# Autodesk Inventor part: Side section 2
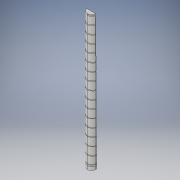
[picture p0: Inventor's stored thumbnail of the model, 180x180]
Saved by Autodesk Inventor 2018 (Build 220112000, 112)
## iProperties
Created: 2018-10
Part Number: Side section 2
Material: Generic
Document SubType Name: Modeling
Designer: johne
Density: 1 g/cm^3
Appearance: Default
Author: johne
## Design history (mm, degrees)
sketch "Sketch1"
  geometry: L1 (0, 0)-(25.4, 0); L2 (25.4, 0)-(25.4, -76.2); L3 (25.4, -76.2)-(0, -76.2); L4 (0, -76.2)-(0, 0)
  constraints: 8 end point, 2 parallel, 1 horizontal, 1 perpendicular
  dimensions: "d0" = 25.4 distance of L2.end L3.end; "d1" = 76.2 distance of L1.end L2.end
extrude "Extrusion1" new body sketch "Sketch1" distance "d2" = 25.4; taper "d3" = 0 deg
sketch "Sketch3"
  geometry: L1 (-2.627, -64.34)-(-23.226, -64.34); L2 (-23.226, -64.34)-(-23.226, -10.419); L3 (-23.226, -10.419)-(-2.627, -10.419); L4 (-2.627, -10.419)-(-2.627, -64.34); 1 further point
  constraints: 8 end point, 2 parallel, 1 horizontal, 1 perpendicular
extrude "Extrusion2" join sketch "Sketch3" distance "d4" = 25.4; taper "d5" = 0 deg
sketch "Sketch4"
  geometry: L1 (9.188, -40.142)-(9.188, 0); L2 (65.781, 0)-(-10.419, 0) reference; L3 (49.65, -33.733)-(49.65, 0); L4 (49.65, -33.733)-(75.988, -33.733); L5 (75.988, -33.733)-(75.988, 0); L6 (75.988, 0)-(49.65, 0); L7 (49.65, 0)-(49.65, -33.733); L8 (9.188, 0)-(-27.007, 0); L9 (-27.007, 0)-(-27.007, -40.142); L10 (-27.007, -40.142)-(9.188, -40.142); L11 (9.188, -40.142)-(9.188, 0); A1 r 0.762 centre (49.65, -33.733) between (49.77, -34.486) and (49.531, -32.981) reference; A2 r 0.762 centre (9.188, -40.142) between (9.846, -39.758) and (8.53, -40.527) reference; 1 further point
  constraints: 20 end point, 4 parallel, 3 perpendicular, 2 horizontal, 2 point on circle, 2 point on line, 1 centre point, 1 vertical, 4 other
extrude "Extrusion3" cut sketch "Sketch4" distance "d6" = 25.4; taper "d7" = 0 deg
sketch "Sketch5"
  geometry: L1 (17.911, -0.752)-(29.845, -0.752); L2 (29.845, -0.752)-(29.845, 25.4); L3 (29.845, 25.4)-(17.911, 25.4); L4 (17.911, 25.4)-(17.911, -0.752); L5 (2.925, -7.161)-(-11.223, -7.161); L6 (-11.223, -7.161)-(-11.223, 25.4); L7 (-11.223, 25.4)-(2.925, 25.4); L8 (2.925, 25.4)-(2.925, -7.161); 5 further points; 2 other entities
  constraints: 16 end point, 4 parallel, 2 horizontal, 2 perpendicular, 1 point on line, 2 other
extrude "Extrusion4" cut sketch "Sketch5" distance "d8" = 76.2; taper "d9" = 0 deg
sketch "Sketch6"
  geometry: L1 (-20.538, -19.607)-(-20.538, -60.069) reference; L2 (-20.538, -26.89)-(-20.538, -19.607); L3 (-20.538, -19.607)-(-13.045, -19.607); A1 r 7.62 centre (-12.926, -27.226) between (-13.045, -19.607) and (-20.538, -26.89); 1 further point
  constraints: 4 end point, 2 point on circle, 1 centre point, 1 collinear, 1 perpendicular, 2 other
  dimensions: "d10" = 7.62 radius of A1
extrude "Extrusion5" cut sketch "Sketch6" stored distance "d11" = 76.2; taper "d12" = 0 deg
workplane "Work Plane1"
workplane "Work Plane2"
mirror "Mirror1"
mirror "Mirror2"
sketch "Sketch7"
  geometry: L1 (-5.552, -52.785)-(-5.552, -26.89) reference; L2 (-20.538, -26.89)-(-20.538, -52.785) reference; A1 r 7.62 centre (-13.165, -52.45) between (-13.045, -60.069) and (-5.552, -52.785) reference; A2 r 7.62 centre (-13.165, -27.226) between (-5.552, -26.89) and (-13.045, -19.607) reference; A3 r 7.62 centre (-12.926, -27.226) between (-13.045, -19.607) and (-20.538, -26.89) reference; A4 r 7.62 centre (-12.926, -52.45) between (-20.538, -52.785) and (-13.045, -60.069) reference; 1 further point
extrude "Extrusion6" join sketch "Sketch7" distance "d13" = 184.15; taper "d14" = 0 deg
feature "Sculpt1"
sketch "Sketch8"
  geometry: C1 r 0.762 at (0, 0) reference; 1 further point
extrude "Extrusion7" cut sketch "Sketch8" distance "d15" = 184.15; taper "d16" = 0 deg
sketch "Sketch10"
  geometry: L1 (56.593, -27.851)-(56.593, -39.145) reference; L2 (49.31, -25.4)-(56.593, -25.4) reference; L3 (56.593, -25.4)-(62.943, -25.4); L4 (76.2, -25.4)-(0, -25.4) reference; L5 (23.415, -25.4)-(16.131, -25.4) reference; L6 (16.131, -25.4)-(9.781, -25.4); L7 (9.781, -25.4)-(-4.173, -25.4); L8 (-4.173, -25.4)-(-4.173, 6.216); L9 (-4.173, 6.216)-(9.781, 6.216); L10 (9.781, 6.216)-(9.781, -25.4); L11 (62.943, -25.4)-(76.826, -25.4); L12 (76.826, -25.4)-(76.826, 0); L13 (76.826, 0)-(62.943, 0); L14 (62.943, 0)-(62.943, -25.4); 3 further points; 1 other entity
  constraints: 20 end point, 4 parallel, 2 horizontal, 2 perpendicular, 2 point on line, 1 coincident
  dimensions: "d19" = 6.35 distance of L2.end L3.end; "d20" = 6.35 distance of L5.end L6.end
extrude "Extrusion9" cut sketch "Sketch10" distance "d21" = 50.8; taper "d22" = 0 deg
sketch "Sketch11"
  geometry: L1 (0, -25.4)-(53.163, -25.4) reference; L2 (53.163, -25.4)-(53.163, -12.7); L3 (53.163, 0)-(53.163, -25.4) reference; L4 (-7.051, -12.7)-(-7.051, 2.628); L5 (-7.051, 2.628)-(53.163, 2.628); L6 (53.163, 2.628)-(53.163, -12.7); L7 (-7.051, -12.7)-(-7.051, -25.4); L8 (-7.051, -25.4)-(53.163, -25.4); 1 further point
  constraints: 12 end point, 1 midpoint, 1 parallel, 1 perpendicular, 1 vertical
extrude "Extrusion10" cut sketch "Sketch11" distance "d23" = 50.8; taper "d24" = 0 deg
sketch "Sketch14"
  geometry: L1 (-14.986, 25.895)-(-14.986, 0) reference; L2 (0, 0)-(0, 25.895) reference; L3 (-0.375, 25.887)-(-0.375, 0.008); L4 (-14.612, 0.008)-(-14.612, 25.887); A1 r 7.62 centre (-7.613, 25.56) between (0, 25.895) and (-7.493, 33.179) reference; A2 r 7.62 centre (-7.374, 25.56) between (-7.493, 33.179) and (-14.986, 25.895) reference; A3 r 7.62 centre (-7.613, 0.335) between (-7.493, -7.284) and (0, 0) reference; A4 r 7.62 centre (-7.374, 0.335) between (-14.986, 0) and (-7.493, -7.284) reference; A5 r 7.245 centre (-7.613, 25.56) between (-0.375, 25.887) and (-7.493, 32.804); A6 r 7.245 centre (-7.613, 0.335) between (-7.493, -6.909) and (-0.375, 0.008); A7 r 7.245 centre (-7.374, 0.335) between (-14.612, 0.008) and (-7.493, -6.909); A8 r 7.245 centre (-7.374, 25.56) between (-7.493, 32.804) and (-14.612, 25.887); 1 further point
  constraints: 8 point on circle, 4 centre point, 4 end point, 5 other
  dimensions: "d36" = 0.37465 radial gap between concentric circles of A1 A5
extrude "Extrusion13" cut sketch "Sketch14" distance "d37" = 300; taper "d38" = 0 deg
sketch "Sketch15"
  geometry: L1 (-20.164, -26.899)-(-20.164, -52.777) reference; L2 (-5.927, -52.777)-(-5.927, -26.899) reference; L3 (-19.976, -52.773)-(-19.976, -26.903); L4 (-6.114, -26.903)-(-6.114, -52.773); A1 r 7.245 centre (-12.926, -27.226) between (-13.045, -19.981) and (-20.164, -26.899) reference; A2 r 7.245 centre (-12.926, -52.45) between (-20.164, -52.777) and (-13.045, -59.694) reference; A3 r 7.245 centre (-13.165, -52.45) between (-13.045, -59.694) and (-5.927, -52.777) reference; A4 r 7.245 centre (-13.165, -27.226) between (-5.927, -26.899) and (-13.045, -19.981) reference; A5 r 7.058 centre (-12.926, -27.226) between (-13.045, -20.169) and (-19.976, -26.903); A6 r 7.058 centre (-13.165, -27.226) between (-6.114, -26.903) and (-13.045, -20.169); A7 r 7.058 centre (-13.165, -52.45) between (-13.045, -59.507) and (-6.114, -52.773); A8 r 7.058 centre (-12.926, -52.45) between (-19.976, -52.773) and (-13.045, -59.507); 1 further point
  constraints: 8 point on circle, 4 centre point, 4 end point, 5 other
  dimensions: "d39" = 0.18733 distance between parallel lines of L1 L3
loft "Loft1" sketch "Sketch15" dims "d40" = 0, "d41" = 90 deg, "d42" = 0, "d43" = 90 deg
  node "Edges1"
node "Direct Edit2"
sketch "Sketch18"
  geometry: L1 (0, 0)-(0, 24.576) reference; L2 (13.169, 24.576)-(13.169, 0) reference; 3 further points
  constraints: 4 other
extrude "Extrusion16" join sketch "Sketch18" distance "d52" = 5; taper "d53" = 0 deg
workplane "Work Plane3"
workplane "Work Plane4"
workplane "Work Plane5"
workplane "Work Plane6"
workplane "Work Plane7"
sketch "Sketch24"
  geometry: L1 (-24.947, 16.41)-(59.366, 16.41); L2 (59.366, 16.41)-(59.366, -235.464); L3 (59.366, -235.464)-(-24.947, -235.464); L4 (-24.947, -235.464)-(-24.947, 16.41); 1 further point
  constraints: 8 end point, 2 parallel, 1 horizontal, 1 perpendicular
extrude "Extrusion20" cut sketch "Sketch24" distance "d69" = 100; taper "d70" = 0 deg
body "Solid1"
node "Reference1"
node "Reference2"
node "Reference3"
node "Projected Loop1"
node "Projected Loop2"
node "Projected Loop3"
feature "Composite1"
body "Srf1"
feature "Scale2"
other parameters: "d45" = 9.5, "d46" = 9.5
